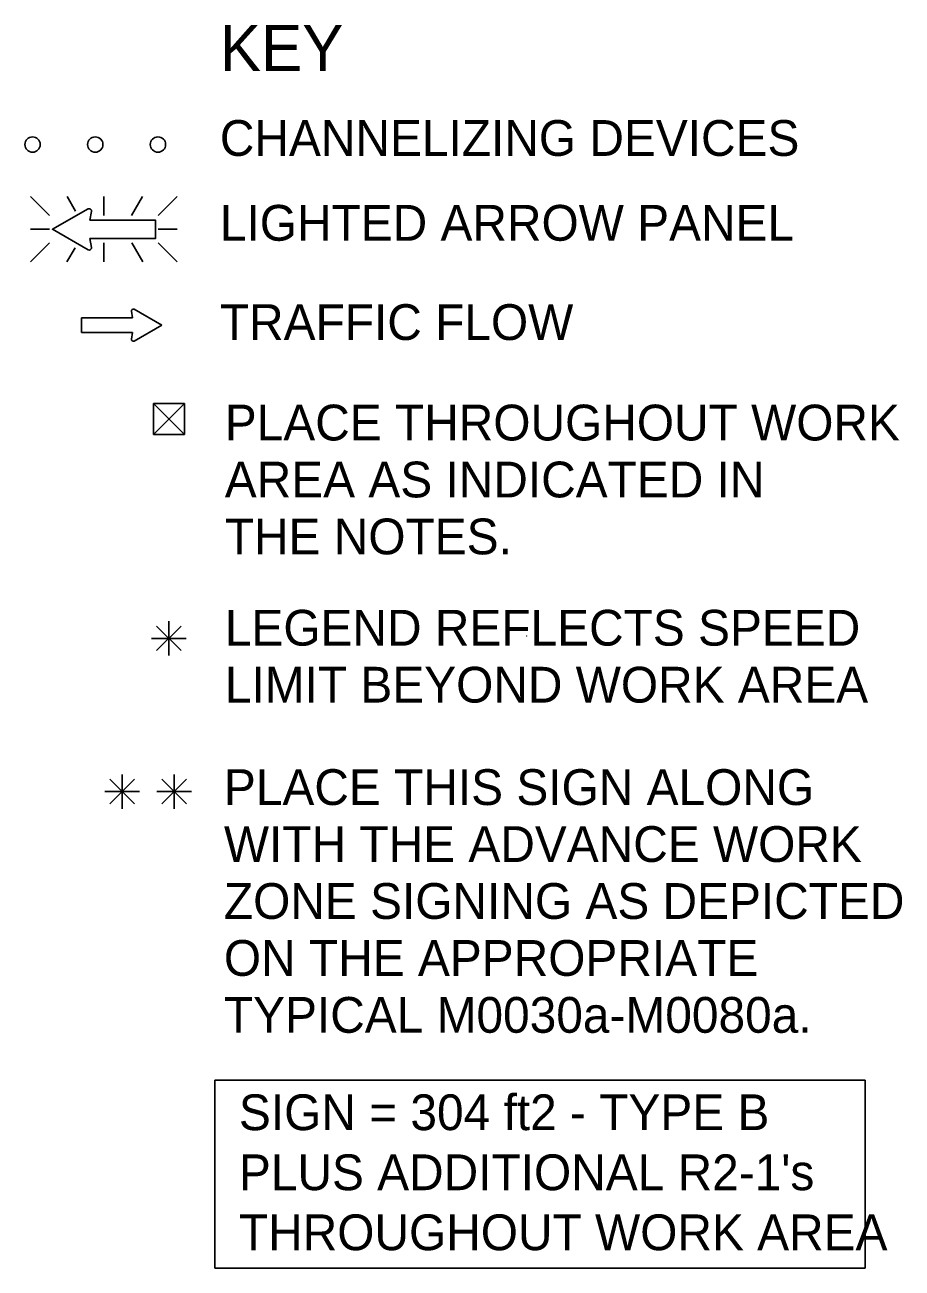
# Model space of a CAD drawing. Extents: x 16730 to 18479, y 5752 to 6927.
# Drawn here: x 17195.1 to 17423.1, y 6585.1 to 6908.3 of the extents above; entities that cross this region are included whole.
import ezdxf

# ---------------------------------------------------------------- set-up
doc = ezdxf.new("R2010")
doc.units = 0
for name, color, linetype in [('MT_SCRATCH_LEVEL_E', 7, 'Continuous'), ('TRAFFIC_SIGNS_PR', 7, 'Continuous'), ('TYPICAL_TEXT_DIMEN_EX', 7, 'Continuous'), ('TYPICAL_TEXT_DIMEN_PR', 7, 'Continuous')]:
    doc.layers.add(name, color=color, linetype=linetype)

msp = doc.modelspace()

# ---------------------------------------------------------------- linework, layer by layer
at = {"layer": 'MT_SCRATCH_LEVEL_E'}
for p, q in [((17230.68, 6830.23), (17223.44, 6834.34)), ((17223.07, 6832.08), (17209.82, 6832.08)), ((17209.82, 6832.08), (17209.82, 6828.34)), ((17222.76, 6833.86), (17223.07, 6832.08)), ((17209.82, 6828.34), (17223.07, 6828.34)), ((17223.07, 6828.34), (17222.76, 6826.56)), ((17223.44, 6826.08), (17230.68, 6830.23))]:
    msp.add_line(p, q, dxfattribs=at)
for centre, start, end in [((17223.22, 6833.93), 60.4248, 189.9638), ((17223.22, 6826.49), 170.0362, 299.7731)]:
    msp.add_arc(centre, 0.463, start, end, dxfattribs=at)
at = {"layer": 'TRAFFIC_SIGNS_PR'}
for p, q in [((17196.5, 6863.61), (17201.43, 6858.68)), ((17208.26, 6859.79), (17206.05, 6863.61)), ((17215.58, 6858.68), (17215.58, 6863.61)), ((17222.81, 6858.68), (17225.66, 6863.61)), ((17229.73, 6858.68), (17234.66, 6863.61)), ((17201.43, 6855.12), (17196.5, 6855.12)), ((17229.73, 6855.12), (17234.66, 6855.12)), ((17196.5, 6846.64), (17201.43, 6851.57)), ((17215.58, 6851.57), (17215.58, 6846.63)), ((17225.71, 6846.63), (17222.86, 6851.57)), ((17229.73, 6851.57), (17234.66, 6846.63)), ((17206.01, 6846.63), (17208.12, 6850.29))]:
    msp.add_line(p, q, dxfattribs=at)
for points in [[(17211.51, 6860.4), (17202.22, 6855.12), (17211.51, 6849.8)], [(17212.38, 6850.43), (17211.98, 6852.7), (17228.99, 6852.7), (17228.99, 6857.5), (17211.98, 6857.5), (17212.38, 6859.78)]]:
    msp.add_lwpolyline(points, dxfattribs=at)
for centre in [(17197.06, 6877.15), (17213.36, 6877.15), (17229.66, 6877.15)]:
    msp.add_circle(centre, 2, dxfattribs=at)
for centre, radius, start, end in [((17211.8, 6859.88), 0.598, 350.7308, 118.8916), ((17211.79, 6850.33), 0.597, 241.4833, 9.9593)]:
    msp.add_arc(centre, radius, start, end, dxfattribs=at)
at = {"layer": 'TYPICAL_TEXT_DIMEN_EX'}
msp.add_lwpolyline([(17244.47, 6633.95), (17413.48, 6633.95), (17413.48, 6585.12), (17244.47, 6585.12)], close=True, dxfattribs=at)
at = {"layer": 'TYPICAL_TEXT_DIMEN_PR'}
for p, q in [((17228.53, 6809.82), (17236.53, 6801.82)), ((17228.53, 6801.82), (17236.53, 6809.82)), ((17229.3, 6751.99), (17235.68, 6745.62)), ((17235.68, 6751.99), (17229.3, 6745.62)), ((17232.49, 6748.81), (17232.49, 6753.26)), ((17232.49, 6748.81), (17227.96, 6748.81)), ((17232.49, 6748.81), (17235.68, 6748.81)), ((17232.49, 6748.81), (17236.97, 6748.81)), ((17232.49, 6748.81), (17232.49, 6744.31)), ((17223.54, 6712.18), (17217.16, 6705.8)), ((17217.17, 6712.18), (17223.54, 6705.8)), ((17220.35, 6708.99), (17220.35, 6713.44)), ((17230.67, 6712.18), (17237.05, 6705.8)), ((17237.05, 6712.18), (17230.67, 6705.8)), ((17233.86, 6708.99), (17233.86, 6713.44)), ((17220.35, 6708.99), (17215.82, 6708.99)), ((17220.35, 6708.99), (17223.54, 6708.99)), ((17220.35, 6708.99), (17224.83, 6708.99)), ((17220.35, 6708.99), (17220.35, 6704.49)), ((17233.86, 6708.99), (17229.33, 6708.99)), ((17233.86, 6708.99), (17237.05, 6708.99)), ((17233.86, 6708.99), (17238.34, 6708.99)), ((17233.86, 6708.99), (17233.86, 6704.49))]:
    msp.add_line(p, q, dxfattribs=at)
msp.add_lwpolyline([(17228.53, 6809.82), (17228.53, 6801.82), (17236.53, 6801.82), (17236.53, 6809.82)], close=True, dxfattribs=at)
msp.add_open_spline([(17325.44, 6749.39), (17325.46, 6749.39), (17325.47, 6749.39), (17325.47, 6749.39)], degree=2, dxfattribs=at)

# ---------------------------------------------------------------- texts
at = {"layer": 'TYPICAL_TEXT_DIMEN_EX'}
for s, height, p in [('KEY', 12, (17245.75, 6896.25)), ('CHANNELIZING DEVICES', 9.3, (17245.75, 6874.2)), ('LIGHTED ARROW PANEL', 9.3, (17245.75, 6852.15)), ('TRAFFIC FLOW', 9.3, (17245.75, 6826.35)), ('PLACE THROUGHOUT WORK', 9.3, (17247.03, 6800.24)), ('AREA AS INDICATED IN', 9.3, (17247.03, 6785.44)), ('THE NOTES.', 9.3, (17247.03, 6770.64)), ('LEGEND REFLECTS SPEED', 9.3, (17247.04, 6746.91)), ('LIMIT BEYOND WORK AREA', 9.3, (17247.04, 6732.11)), ('PLACE THIS SIGN ALONG', 9.3, (17246.8, 6705.49)), ('WITH THE ADVANCE WORK', 9.3, (17246.8, 6690.69)), ('ZONE SIGNING AS DEPICTED', 9.3, (17246.8, 6675.89)), ('ON THE APPROPRIATE', 9.3, (17246.8, 6661.09)), ('TYPICAL M0030a-M0080a.', 9.3, (17246.8, 6646.29)), ('SIGN = 304 ft2 - TYPE B', 9.3, (17250.7, 6620.98)), ("PLUS ADDITIONAL R2-1's", 9.3, (17250.7, 6605.38)), ('THROUGHOUT WORK AREA', 9.3, (17250.7, 6589.78))]:
    msp.add_text(s, height=height, dxfattribs=at).set_placement(p)

doc.saveas('drawing.dxf')
